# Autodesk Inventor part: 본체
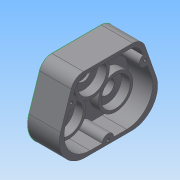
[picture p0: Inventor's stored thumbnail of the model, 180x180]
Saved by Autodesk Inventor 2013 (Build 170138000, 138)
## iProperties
Created: 2014-12
Part Number: 본체
Material: 일반
Document SubType Name: 판금
Designer: Administrator
Density: 1 g/cm^3
Sheet Metal Rule: 기본값
Author: Administrator
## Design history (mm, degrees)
sketch "스케치7"
  geometry: L1 (-47, 95.766)-(47, 95.766); L2 (-81.323, -8.357)-(83.342, -8.357); L3 (-47, 95.766)-(-81.323, -8.357); L4 (47, 95.766)-(83.342, -8.357); L5 (-41.714, 59.766)-(46.616, 59.766); L6 (-71.75, 27.643)-(66.305, 27.643); L7 (0, 59.766)-(79.665, -19.899); L8 (0, 59.766)-(-78.474, -18.708); L9 (-51.288, 27.643)-(46, 27.643); C1 r 24 at (-32.527, 27.24); C2 r 24 at (32.527, 27.24); A1 r 46 centre (0, 59.766) between (-32.527, 27.24) and (32.527, 27.24); 1 further point
  constraints: 18 end point, 4 point on line, 3 centre point, 3 parallel, 2 point on circle, 1 collinear, 1 horizontal
  dimensions: "d39" = 94 distance of L1.start L1.end; "d41" = 36 distance between parallel lines of L5 L1; "d42" = 36 vertical distance of L2.end L6.end; "d43" = 47 horizontal distance of L1.end point (0, 0); "d109" = 92 diameter of A1; "d110" = 45 deg angle of L7 L5; "d111" = 90 deg angle of L8 L7; "d112" = 48 diameter of C1; "d113" = 48 diameter of C2
extrude "돌출3" new body sketch "스케치7" distance "d44" = 44; taper "d45" = 0 deg
sketch "스케치8"
  geometry: L1 (-95.766, 47)-(-95.766, -47) reference; L2 (8.357, -81.323)-(8.357, 83.342) reference; L3 (-90.766, 42)-(-90.766, -42); L4 (3.357, 78.342)-(3.357, -76.323); L5 (-90.766, 42)-(3.357, 78.342); L6 (-90.766, -42)-(3.357, -76.323); 1 further point
  constraints: 8 end point, 2 parallel
  dimensions: "d46" = 5 distance between parallel lines of L3 L1; "d47" = 5 distance between parallel lines of L2 L4; "d48" = 5 horizontal distance of L3.start L1.start; "d49" = 5 horizontal distance of L3.end L1.end; "d50" = 5 horizontal distance of L4.start L2.end; "d51" = 5 horizontal distance of L2.start L4.end
extrude "돌출4" cut sketch "스케치8" distance "d52" = 34; taper "d53" = 0 deg
sketch "스케치9"
  geometry: L1 (3.357, 78.342)-(3.357, -76.323) reference; L2 (-59.766, -37.087)-(-59.766, 37.087); L3 (-95.766, 47)-(-95.766, -47) reference; L4 (-27.643, -62.206)-(-27.643, 91.792); L5 (8.357, -81.323)-(8.357, 83.342) reference; L6 (-59.766, 0)-(3.357, 0); C1 r 20 at (-59.766, 0); C2 r 10 at (-59.766, 0); C3 r 24 at (-59.766, 0); 2 further points
  constraints: 6 end point, 3 centre point, 3 coincident, 2 parallel, 1 midpoint, 1 perpendicular, 1 point on line
  dimensions: "d56" = 36 distance from line of L3 L2.end; "d66" = 36 distance between parallel lines of L5 L4
extrude "돌출5" join sketch "스케치9" distance "d67" = 12; taper "d68" = 0 deg
extrude "돌출6" cut sketch "스케치9" distance "d69" = 3; taper "d70" = 0 deg
extrude "돌출7" join sketch "스케치9" distance "d71" = 12; taper "d72" = 0 deg
sketch "스케치10"
  geometry: L1 (-90.766, -42)-(-90.766, 42) reference; L2 (3.357, -76.323)-(-90.766, -42) reference; L3 (3.357, 78.342)-(3.357, -76.323) reference; L4 (-90.766, 42)-(3.357, 78.342) reference; L5 (-59.766, 0)-(18.438, 78.204); L6 (-59.766, 0)-(17.496, -77.263); L7 (-59.766, -37.087)-(-59.766, 37.087) reference; C1 r 24 at (-59.766, 0) reference; 1 further point
  constraints: 4 end point
  dimensions: "d73" = 90 deg angle of L5 L6; "d74" = 45 deg angle of L6 L7
fillet "모깎기3" dims "d75" = 18
fillet "모깎기4" dims "d76" = 18
fillet "모깎기5" dims "d77" = 36
sketch "스케치11"
  geometry: L1 (-79.25, 46.447)-(-45.61, 59.435) reference; L2 (-44.977, -58.698)-(-78.933, -46.315) reference; L3 (3.357, 25.852)-(3.357, -24.876) reference; L4 (-66.766, 51.267)-(-66.766, -50.752); L5 (-95.766, 34.218)-(-95.766, -33.981) reference; L6 (0, 0)-(77.153, 0); L7 (3.357, 25.852)-(3.357, -24.876) reference; A1 r 8 centre (-66.766, -50.752) between (-59.251, -53.493) and (-74.282, -48.011); A2 r 8 centre (-66.766, 51.267) between (-74.229, 48.385) and (-59.303, 54.148); A3 r 8 centre (3.357, 0) between (3.357, 8) and (3.357, -8); 3 further points
  constraints: 10 point on line, 6 point on circle, 5 coincident, 4 end point, 3 centre point, 1 parallel, 1 perpendicular
  dimensions: "d79" = 29 distance between parallel lines of L4 L5; "d80" = 16 diameter of A1; "d81" = 16 diameter of A2; "d82" = 16 diameter of A3
extrude "돌출8" join sketch "스케치11" distance "d83" = 34; taper "d84" = 0 deg
sketch "스케치14"
  geometry: L1 (95.766, -33.981)-(95.766, 34.218) reference; 2 further points
  constraints: 1 horizontal alignment, 1 other
  dimensions: "d88" = 30 distance from line of point (65.766, 0) L1
feature "엠보싱1" sketch "스케치14" dims "d39" = 94, "d41" = 36, "d42" = 36, "d43" = 47, "d92" = 1, "d93" = 0, "d109" = 92, "d110" = 45 deg, "d111" = 90 deg, "d112" = 48, "d113" = 48
sketch "스케치15"
  geometry: L1 (-8.357, 32.647)-(-8.357, -31.551) reference; L2 (38.914, -65.741)-(83.402, -51.076) reference; L3 (95.766, -33.981)-(95.766, 34.218) reference; L4 (83.698, 51.212)-(39.507, 66.636) reference; L5 (66.031, -18.016)-(64.46, -18.016) reference; L6 (64.704, -21.598)-(64.256, -21.655) reference; L7 (63.979, -17.479)-(68.335, -17.479) reference; L8 (68.335, -17.479)-(68.335, -20.955) reference; L9 (68.335, -20.955)-(67.887, -20.955) reference; L10 (67.887, -20.955)-(67.887, -18.016) reference; L11 (67.887, -18.016)-(66.479, -18.016) reference; L12 (66.479, -18.016)-(66.479, -20.638) reference; L13 (66.479, -20.638)-(66.031, -20.638) reference; L14 (66.031, -20.638)-(66.031, -18.016) reference; L15 (69.019, -14.939)-(63.768, -14.939) reference; L16 (63.768, -14.939)-(63.768, -14.393) reference; L17 (63.768, -14.393)-(69.271, -14.393) reference; L18 (69.271, -14.393)-(69.271, -14.825) reference; L19 (68.897, -13.547)-(64.069, -13.547) reference; L20 (64.069, -13.547)-(64.069, -13.001) reference; L21 (64.069, -13.001)-(66.975, -13.001) reference; L22 (66.975, -13.001)-(66.975, -11.764) reference; L23 (66.975, -11.764)-(67.391, -11.764) reference; L24 (67.391, -11.764)-(67.391, -13.001) reference; L25 (67.391, -13.001)-(69.182, -13.001) reference; L26 (69.182, -13.001)-(69.182, -13.449) reference; L27 (62.612, -15.11)-(62.164, -15.11) reference; L28 (62.164, -15.11)-(62.164, -9.924) reference; L29 (62.164, -9.924)-(64.46, -9.924) reference; L30 (64.46, -9.924)-(64.46, -10.323) reference; L31 (64.216, -10.461)-(62.612, -10.461) reference; L32 (62.612, -10.461)-(62.612, -15.11) reference; L33 (65.469, -12.497)-(65.054, -12.13) reference; L34 (64.81, -8.898)-(65.217, -8.524) reference; L35 (68.954, -10.404)-(68.954, -10.885) reference; L36 (64.59, -7.237)-(64.59, -7.775) reference; L37 (66.878, -7.726)-(66.878, -7.18) reference; L38 (68.628, -1.832)-(68.131, -1.832) reference; L39 (68.131, -1.832)-(68.131, 0.041) reference; L40 (68.131, 0.041)-(62.628, 0.041) reference; L41 (62.628, 0.041)-(62.628, 0.586) reference; L42 (62.628, 0.586)-(68.131, 0.586) reference; L43 (68.131, 0.586)-(68.131, 2.45) reference; L44 (68.131, 2.45)-(68.628, 2.45) reference; L45 (68.628, 2.45)-(68.628, -1.832) reference; L46 (64.745, 12.114)-(64.745, 9.94) reference; L47 (64.745, 9.94)-(62.197, 9.94) reference; L48 (62.197, 9.94)-(62.197, 10.494) reference; L49 (62.197, 10.494)-(64.297, 10.494) reference; L50 (64.297, 10.494)-(64.297, 15.094) reference; L51 (64.297, 15.094)-(64.745, 15.094) reference; L52 (64.745, 15.094)-(64.745, 12.659) reference; L53 (64.745, 12.659)-(66.21, 12.659) reference; L54 (66.21, 12.659)-(66.21, 15.973) reference; L55 (66.21, 15.973)-(66.658, 15.973) reference; L56 (66.658, 15.973)-(66.658, 10.73) reference; L57 (68.661, 10.388)-(68.661, 14.955) reference; L58 (68.661, 14.955)-(69.117, 14.955) reference; L59 (69.117, 14.955)-(69.117, 9.81) reference; L60 (66.658, 10.136)-(66.658, 8.768) reference; L61 (66.658, 8.768)-(66.21, 8.768) reference; L62 (66.21, 8.768)-(66.21, 12.114) reference; L63 (66.21, 12.114)-(64.745, 12.114) reference; L64 (62.628, 3.501)-(64.46, 4.168) reference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; A1 r 36 centre (27.643, 32.647) between (39.507, 66.636) and (-8.357, 32.647) reference; A2 r 36 centre (27.643, -31.551) between (-8.357, -31.551) and (38.914, -65.741) reference; A3 r 18 centre (77.766, -33.981) between (83.402, -51.076) and (95.766, -33.981) reference; A4 r 18 centre (77.766, 34.218) between (95.766, 34.218) and (83.698, 51.212) reference; 54 further points
  constraints: 68 other
sketch "스케치16"
  geometry: L1 (3.357, 25.852)-(3.357, 8) reference; L2 (-59.766, 0)-(-59.766, 39.774); L3 (-7.973, 51.794)-(-59.766, 0); L4 (-59.766, 0)-(4.694, -64.461); L5 (-27.24, -32.527)-(-27.24, 32.527); C1 r 24 at (-59.766, 0) reference; C2 r 24 at (-27.24, -32.527); C3 r 24 at (-27.24, 32.527); A1 r 46 centre (-59.766, 0) between (-27.24, -32.527) and (-27.24, 32.527); 1 further point
  constraints: 8 end point, 3 centre point, 2 point on circle, 2 point on line, 1 coincident, 1 parallel
  dimensions: "d98" = 46 radius of A1; "d103" = 45 deg angle of L3 L2; "d105" = 90 deg angle of L3 L4; "d107" = 48 diameter of C2; "d108" = 48 diameter of C3
extrude "돌출9" join sketch "스케치16" distance "d114" = 12; taper "d115" = 0 deg
sketch "스케치17"
  geometry: C1 r 20 at (-27.24, 32.527); C2 r 20 at (-27.24, -32.527); A1 r 24 centre (-27.24, -32.527) between (-48.351, -21.111) and (-38.655, -11.416) reference; A2 r 24 centre (-27.24, 32.527) between (-38.655, 11.416) and (-48.351, 21.111) reference; 1 further point
  constraints: 2 centre point, 2 coincident
  dimensions: "d116" = 40 diameter of C2; "d118" = 40 diameter of C1
extrude "돌출10" cut sketch "스케치17" distance "d119" = 12; taper "d120" = 0 deg
sketch "스케치20"
  geometry: C1 r 10 at (-59.766, 0) reference; C2 r 20 at (-59.766, 0); 1 further point
  constraints: 1 centre point, 1 coincident
  dimensions: "d125" = 40 diameter of C2
extrude "돌출11" cut sketch "스케치20" distance "d127" = 12; taper "d128" = 0 deg
sketch "스케치21"
  geometry: C1 r 20 at (0, 0) reference; C2 r 10 at (0, 0); 1 further point
  constraints: 1 centre point, 1 coincident
  dimensions: "d129" = 20 diameter of C2
sketch "스케치22"
  geometry: C1 r 20 at (0, 0) reference; C2 r 10 at (0, 0); 1 further point
  constraints: 1 centre point, 1 coincident
  dimensions: "d131" = 20 diameter of C2
extrude "돌출12" cut sketch "스케치21" stored distance "d133" = 12; taper "d134" = 0 deg
extrude "돌출13" cut sketch "스케치22" stored distance "d135" = 12; taper "d136" = 0 deg
sketch "스케치25"
  geometry: C1 r 10 at (27.24, -32.527) reference; C2 r 15 at (27.643, 32.647); C3 r 15 at (27.24, -32.527); C4 r 20 at (27.643, 32.647); C5 r 20 at (27.24, -32.527); A1 r 36 centre (27.643, 32.647) between (39.507, 66.636) and (-8.357, 32.647) reference; 1 further point
  constraints: 4 centre point, 4 coincident
  dimensions: "d144" = 40 diameter of C5; "d146" = 40 diameter of C4; "d147" = 30 diameter of C2; "d148" = 30 diameter of C3
extrude "돌출15" join sketch "스케치25" distance "d149" = 7; taper "d150" = 0 deg
sketch "스케치26"
  geometry: A1 r 8 centre (-66.766, -50.752) between (-59.251, -53.493) and (-74.282, -48.011) reference; A2 r 8 centre (-66.766, 51.267) between (-74.229, 48.385) and (-59.303, 54.148) reference; A3 r 8 centre (3.357, 0) between (3.357, 8) and (3.357, -8) reference; 4 further points
  constraints: 3 coincident
hole "구멍1" sketch "스케치26" at (-66.766, 51.267), (-66.766, -50.752), (3.357, 0) diameter "d151" = 4.134; stored, may be unused: countersink angle "d155" = 90 deg, drill point angle "d157" = 118 deg; dims "d152" = 20, "d153" = 4, "d154" = 2, "d156" = 23
node "솔리드2"
other parameters: "K계수" = 4.4, "BendRadius" = 0.5 (derived), "BendReliefWidth" = 0.5 (derived), "BendReliefDepth" = 0.25 (derived), "CornerReliefSize" = 2 (derived), "SeamGap" = 0.01, "MinimumRemnant" = 1 (derived), "TransitionRadius" = 0.5 (= BendRadius)
